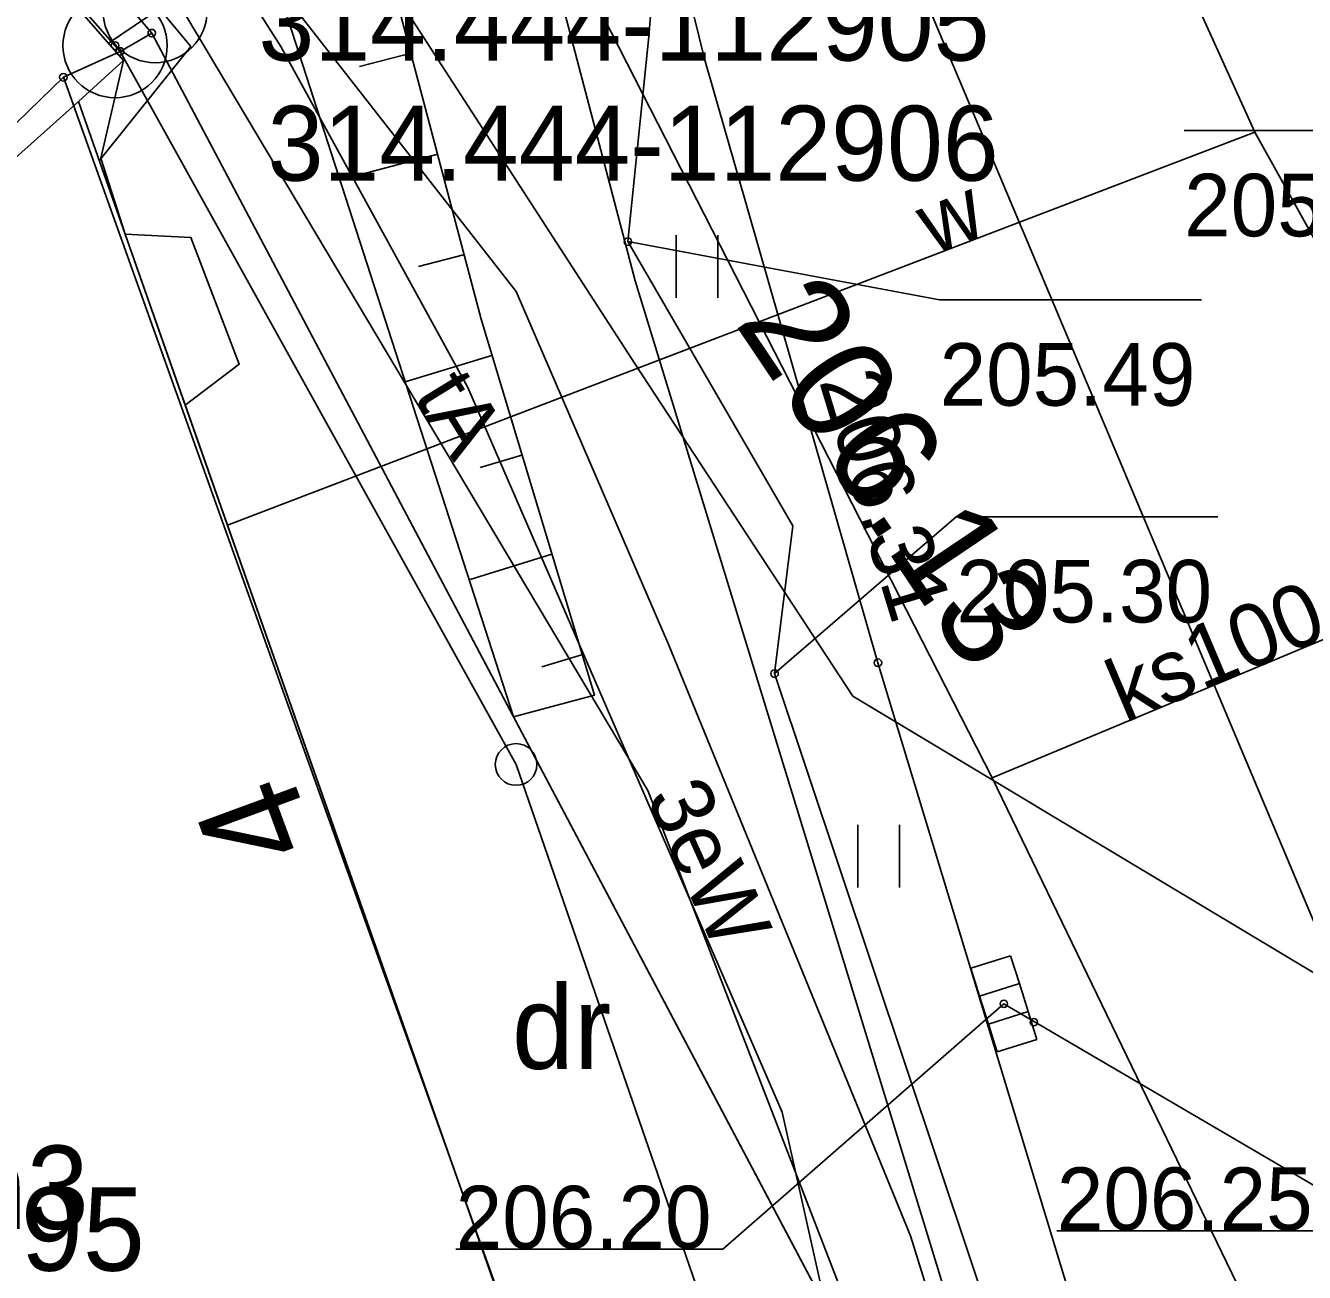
# Model space of a CAD drawing. Extents: x 6512606 to 6513347, y 6022524 to 6022728.
# Drawn here: x 6512836.96 to 6512852.29, y 6022619.43 to 6022634.38 of the extents above; entities that cross this region are included whole.
import ezdxf

# ---------------------------------------------------------------- set-up
doc = ezdxf.new("R2010")
doc.units = 0
for name, color, linetype in [('121-Punkt osnowy szczegółowej', 7, 'Continuous'), ('121-Punkt osnowy szczegółowej-Atr103', 7, 'Continuous'), ('202-punkt graniczny', 7, 'Continuous'), ('203-punkt graniczny', 7, 'Continuous'), ('210-oznaczenie konturu użytku gruntowego', 7, 'Continuous'), ('216-obręb ewidencyjny', 7, 'Continuous'), ('217-kontur klasyfikacyjny', 7, 'Continuous'), ('218-kontur użytku gruntowego', 7, 'Continuous'), ('219-działka ewidencyjna', 7, 'Continuous'), ('238-Punkt adresowy budynku', 7, 'Continuous'), ('312-budynek ewidencyjny', 7, 'Continuous'), ('312-oznaczenie budynku ewidencyjnego', 7, 'Continuous'), ('312-oznaczenie budynku ewidencyjnego-Atr117', 7, 'Continuous'), ('4', 7, 'Continuous'), ('423-Schody przy drogach  chodnikach', 7, 'Continuous'), ('820-Skarpa nieumocniona', 7, 'Continuous'), ('823-Szczyt skarpy nieumocninej', 7, 'Continuous'), ('824-Podnóże skarpy nieumocninej', 7, 'Continuous'), ('940-Trawnik symb. poj.', 7, 'Continuous'), ('chodnik (powierzchnia)', 7, 'Continuous'), ('Default', 7, 'Continuous'), ('kratka ściekowa (punkt)', 7, 'Continuous'), ('krawężnik (linia)', 7, 'Continuous'), ('przewód ciepłowniczy (linia)', 7, 'Continuous'), ('przewód elektroenergetyczny (linia)', 7, 'Continuous'), ('przewód elektroenergetyczny (linia)-Atr1', 7, 'Continuous'), ('przewód gazowy (linia)', 7, 'Continuous'), ('przewód kanalizacyjny (linia)', 7, 'Continuous'), ('przewód kanalizacyjny (linia)-Atr1', 7, 'Continuous'), ('przewód telekomunikacyjny (linia)', 7, 'Continuous'), ('przewód telekomunikacyjny (linia)-Atr1', 7, 'Continuous'), ('przewód wodociągowy (linia)', 7, 'Continuous'), ('przewód wodociągowy (linia)-Atr1', 7, 'Continuous'), ('punkt o określonej wysokości (sieć gazowa)', 7, 'Continuous'), ('punkt o określonej wysokości (sieć gazowa)-Atr2', 7, 'Continuous'), ('punkt o określonej wysokości (sieć gazowa)-Atr3', 7, 'Continuous'), ('punkt o określonej wysokości (sieć kanalizacyjna)', 7, 'Continuous'), ('punkt o określonej wysokości (sieć kanalizacyjna)-Atr2', 7, 'Continuous'), ('punkt o określonej wysokości (sieć wodociągowa)', 7, 'Continuous'), ('punkt wysokościowy sztuczny', 7, 'Continuous'), ('punkt wysokościowy sztuczny-Atr2', 7, 'Continuous'), ('rura ochronna - przewód gazowy (linia)', 7, 'Continuous')]:
    doc.layers.add(name, color=color, linetype=linetype)

# ---------------------------------------------------------------- blocks, each defined once
blk = doc.blocks.new('203')
at = {"layer": 'Default'}
blk.add_circle((0, 0), 0.45, dxfattribs=at)
blk = doc.blocks.new('202')
at = {"layer": 'Default'}
blk.add_circle((0, 0), 2.5, dxfattribs=at)
blk = doc.blocks.new('PW01')
at = {"layer": 'Default'}
blk.add_circle((0, 0), 0.45, dxfattribs=at)
blk = doc.blocks.new('US05')
at = {"layer": 'Default'}
for p, q in [((-5.25, -2.5), (-5.25, 2.5)), ((-5.25, 2.5), (-1.75, 2.5)), ((-1.75, -2.5), (-1.75, 2.5)), ((-1.75, 2.5), (1.75, 2.5)), ((1.75, -2.5), (1.75, 2.5)), ((1.75, 2.5), (5.25, 2.5)), ((5.25, -2.5), (5.25, 2.5)), ((-5.25, -2.5), (-1.75, -2.5)), ((-1.75, -2.5), (1.75, -2.5)), ((1.75, -2.5), (5.25, -2.5))]:
    blk.add_line(p, q, dxfattribs=at)
blk = doc.blocks.new('940P')
at = {"layer": 'Default'}
for p, q in [((-2.5, -3.75), (-2.5, 3.75)), ((2.5, -3.75), (2.5, 3.75))]:
    blk.add_line(p, q, dxfattribs=at)
blk = doc.blocks.new('PW02')
at = {"layer": 'Default'}
blk.add_circle((0, 0), 0.45, dxfattribs=at)
blk = doc.blocks.new('121')
at = {"layer": 'Default'}
for radius in [6.25, 0.45]:
    blk.add_circle((0, 0), radius, dxfattribs=at)

msp = doc.modelspace()

# ---------------------------------------------------------------- linework, layer by layer
at = {"layer": '216-obręb ewidencyjny'}
for points in [[(6512836.687, 6022675.173), (6512833.61, 6022675.02), (6512828.67, 6022670.98), (6512801.96, 6022670.34), (6512810.18, 6022663.28), (6512825.37, 6022649.66), (6512838.47, 6022634.29), (6512852.25, 6022608.25), (6512853.17, 6022604.51), (6512855.78, 6022583.95), (6512858.85, 6022571.74), (6512828.23, 6022562.62), (6512818.47, 6022559.72), (6512824.714, 6022553.406)], [(6512852.25, 6022608.25), (6512838.47, 6022634.29), (6512825.37, 6022649.66), (6512810.18, 6022663.28), (6512801.96, 6022670.34), (6512796.96, 6022674.74), (6512790.49, 6022674.74), (6512785.56, 6022674.74), (6512768.24, 6022674.27), (6512754.87, 6022673.72), (6512745.51, 6022673.33), (6512735.76, 6022672.94), (6512730.35, 6022672.71), (6512725.78, 6022672.95), (6512702.575, 6022674.177)]]:
    msp.add_lwpolyline(points, dxfattribs=at)
at = {"layer": '217-kontur klasyfikacyjny'}
for points in [[(6512837.41, 6022633.76), (6512831.54, 6022628.06)], [(6512848.55, 6022602.62), (6512837.41, 6022633.76)]]:
    msp.add_lwpolyline(points, dxfattribs=at)
at = {"layer": '218-kontur użytku gruntowego'}
for points in [[(6512838.47, 6022634.29), (6512825.37, 6022649.66)], [(6512825.37, 6022649.66), (6512838.47, 6022634.29)], [(6512838.09, 6022634.07), (6512824.77, 6022649.17)], [(6512824.77, 6022649.17), (6512838.09, 6022634.07)], [(6512838.09, 6022634.07), (6512838.47, 6022634.29)], [(6512838.47, 6022634.29), (6512838.09, 6022634.07)], [(6512852.25, 6022608.25), (6512838.47, 6022634.29)], [(6512838.47, 6022634.29), (6512852.25, 6022608.25)], [(6512837.41, 6022633.76), (6512838.09, 6022634.07)], [(6512838.09, 6022634.07), (6512837.41, 6022633.76)], [(6512842.84, 6022625.52), (6512838.09, 6022634.07)], [(6512838.09, 6022634.07), (6512842.84, 6022625.52)], [(6512831.54, 6022628.06), (6512837.41, 6022633.76)], [(6512837.41, 6022633.76), (6512831.54, 6022628.06)], [(6512848.55, 6022602.62), (6512837.41, 6022633.76)], [(6512837.41, 6022633.76), (6512848.55, 6022602.62)], [(6512850.47, 6022603.45), (6512842.84, 6022625.52)], [(6512842.84, 6022625.52), (6512850.47, 6022603.45)]]:
    msp.add_lwpolyline(points, dxfattribs=at)
at = {"layer": '219-działka ewidencyjna'}
for points in [[(6512838.47, 6022634.29), (6512825.37, 6022649.66)], [(6512824.77, 6022649.17), (6512838.09, 6022634.07)], [(6512838.47, 6022634.29), (6512838.09, 6022634.07)], [(6512838.47, 6022634.29), (6512852.25, 6022608.25)], [(6512837.41, 6022633.76), (6512838.09, 6022634.07)], [(6512842.84, 6022625.52), (6512838.09, 6022634.07)], [(6512831.54, 6022628.06), (6512837.41, 6022633.76)], [(6512848.55, 6022602.62), (6512837.41, 6022633.76)], [(6512842.84, 6022625.52), (6512850.47, 6022603.45)]]:
    msp.add_lwpolyline(points, dxfattribs=at)
at = {"layer": '312-budynek ewidencyjny'}
for points in [[(6512824.72, 6022649.31), (6512838.13, 6022633.96)], [(6512838.13, 6022633.96), (6512837.59, 6022633.47)], [(6512837.59, 6022633.47), (6512831.54, 6022628.06)], [(6512831.54, 6022628.06), (6512837.59, 6022633.47)], [(6512837.59, 6022633.47), (6512844.01, 6022615.23)]]:
    msp.add_lwpolyline(points, dxfattribs=at)
at = {"layer": '4'}
for points in [[(6512838.47, 6022634.29), (6512825.37, 6022649.66)], [(6512824.77, 6022649.17), (6512838.09, 6022634.07)], [(6512838.47, 6022634.29), (6512838.09, 6022634.07)], [(6512838.47, 6022634.29), (6512852.25, 6022608.25)], [(6512837.41, 6022633.76), (6512838.09, 6022634.07)], [(6512842.84, 6022625.52), (6512838.09, 6022634.07)], [(6512831.54, 6022628.06), (6512837.41, 6022633.76)], [(6512848.55, 6022602.62), (6512837.41, 6022633.76)], [(6512842.84, 6022625.52), (6512850.47, 6022603.45)]]:
    msp.add_lwpolyline(points, dxfattribs=at)
at = {"layer": '423-Schody przy drogach  chodnikach'}
for p, q in [((6512838.15, 6022631.88), (6512838.87, 6022629.83)), ((6512838.94, 6022631.84), (6512838.15, 6022631.88)), ((6512839.52, 6022630.32), (6512838.94, 6022631.84)), ((6512838.87, 6022629.83), (6512839.52, 6022630.32))]:
    msp.add_line(p, q, dxfattribs=at)
at = {"layer": '820-Skarpa nieumocniona'}
for p, q in [((6512841.58, 6022634.05), (6512840.96, 6022633.89)), ((6512841.9, 6022632.84), (6512840.73, 6022632.53)), ((6512842.21, 6022631.63), (6512841.67, 6022631.49)), ((6512842.56, 6022630.43), (6512841.51, 6022630.11)), ((6512842.91, 6022629.23), (6512842.41, 6022629.08)), ((6512843.27, 6022628.04), (6512842.29, 6022627.74)), ((6512843.64, 6022626.84), (6512843.15, 6022626.69))]:
    msp.add_line(p, q, dxfattribs=at)
at = {"layer": '823-Szczyt skarpy nieumocninej'}
msp.add_lwpolyline([(6512833.8, 6022651.69), (6512834.92, 6022648.19), (6512835.69, 6022646.2), (6512839.8, 6022638.81), (6512840.88, 6022636.68), (6512842.42, 6022630.86), (6512843.78, 6022626.35)], dxfattribs=at)
at = {"layer": '824-Podnóże skarpy nieumocninej'}
msp.add_lwpolyline([(6512843.78, 6022626.35), (6512842.81, 6022626.09), (6512839.81, 6022635.37), (6512839.21, 6022636.76), (6512838.73, 6022638.25), (6512834.42, 6022645.85), (6512833.69, 6022648.06), (6512833.8, 6022651.69)], dxfattribs=at)
at = {"layer": 'chodnik (powierzchnia)'}
msp.add_lwpolyline([(6512845.61, 6022610.5), (6512844.69, 6022613.44), (6512844.06, 6022613.28), (6512843.41, 6022615.01), (6512844.01, 6022615.23), (6512838.87, 6022629.83), (6512839.52, 6022630.32), (6512838.94, 6022631.84), (6512838.15, 6022631.88), (6512837.86, 6022632.79), (6512838.13, 6022633.96), (6512826.89, 6022646.81), (6512825.11, 6022648.85), (6512824.32, 6022649.76), (6512820.29, 6022654.03), (6512817.62, 6022656.88), (6512816.1, 6022658.5), (6512810.3, 6022663.44), (6512802.06, 6022670.47), (6512797.05, 6022674.74)], dxfattribs=at)
for points in [[(6512832.77, 6022654.07), (6512832.63, 6022646.82), (6512837.95, 6022638.9), (6512839.21, 6022636.76), (6512839.81, 6022635.37), (6512842.81, 6022626.09), (6512843.78, 6022626.35), (6512842.42, 6022630.86), (6512840.88, 6022636.68), (6512839.84, 6022641.88), (6512838.78, 6022648.12), (6512838.09, 6022653.46), (6512836.3, 6022653.4), (6512834.86, 6022653.53), (6512833.61, 6022653.83)], [(6512840.07, 6022653.59), (6512840.7, 6022648.33), (6512841.69, 6022642.4), (6512842.69, 6022637.33), (6512844.27, 6022631.32), (6512848.17, 6022618.59), (6512848.25, 6022618.32), (6512848.4, 6022617.84), (6512848.64, 6022617), (6512849.8, 6022613.04), (6512850.26, 6022613.71), (6512850.75, 6022614.71), (6512849.55, 6022618.93), (6512847.18, 6022626.74), (6512845.1, 6022633.98), (6512844.14, 6022637.88), (6512843.35, 6022641.83), (6512842.14, 6022649.32), (6512841.8, 6022651.66)]]:
    msp.add_lwpolyline(points, close=True, dxfattribs=at)
at = {"layer": 'krawężnik (linia)'}
msp.add_lwpolyline([(6512841.8, 6022651.66), (6512842.14, 6022649.32), (6512843.35, 6022641.83), (6512844.14, 6022637.88), (6512845.1, 6022633.98), (6512847.18, 6022626.74), (6512849.55, 6022618.93), (6512850.75, 6022614.71)], dxfattribs=at)
at = {"layer": 'przewód ciepłowniczy (linia)'}
msp.add_lwpolyline([(6512852.19, 6022643.78), (6512837.95, 6022634.17)], dxfattribs=at)
at = {"layer": 'przewód elektroenergetyczny (linia)'}
for points in [[(6512702.569, 6022673.878), (6512710.28, 6022673.25), (6512716.66, 6022675.97), (6512746.13, 6022674.3), (6512752.79, 6022674.32), (6512760.61, 6022675.35), (6512763.38, 6022676.06), (6512798.79, 6022676.04), (6512803.06, 6022673.02), (6512807.84, 6022668.96), (6512815.24, 6022662.53), (6512819.98, 6022657.77), (6512831.6, 6022645.79), (6512834.59, 6022642.25), (6512837.06, 6022638.75), (6512840.02, 6022634.13), (6512842.26, 6022630.04), (6512846.03, 6022621.35), (6512846.58, 6022618.9), (6512847.6, 6022616.23), (6512852.12, 6022605.09)], [(6512802.27, 6022673.66), (6512807.42, 6022670.09), (6512811.38, 6022666.87), (6512814.66, 6022663.43), (6512826.4, 6022651.65), (6512827.82, 6022650.09), (6512834.03, 6022642.46), (6512842.84, 6022631.19), (6512844.67, 6022626.95), (6512847.57, 6022619.87), (6512849.81, 6022612.67), (6512853.56, 6022600.08), (6512856.46, 6022588.83), (6512861.26, 6022569.82), (6512861.768, 6022567.654)]]:
    msp.add_lwpolyline(points, dxfattribs=at)
at = {"layer": 'przewód gazowy (linia)'}
msp.add_lwpolyline([(6512847.18, 6022613.76), (6512846.63, 6022615.41), (6512849.08, 6022617.22), (6512845.94, 6022626.61), (6512846.16, 6022628.38), (6512844.18, 6022631.79), (6512844.23, 6022632.26), (6512844.43, 6022634.25), (6512844.47, 6022634.75), (6512844, 6022635.91), (6512842.48, 6022639.61), (6512842.1, 6022640.54), (6512841.83, 6022641.94), (6512833.52, 6022652.16), (6512828.68, 6022655.12), (6512826.33, 6022655.65), (6512824.93, 6022656.06), (6512819.76, 6022660.64)], dxfattribs=at)
at = {"layer": 'przewód kanalizacyjny (linia)'}
for points in [[(6512853.94, 6022620), (6512836.1, 6022662.34)], [(6512825.42, 6022650.35), (6512838.94, 6022634.13)], [(6512853.7, 6022614.72), (6512848.55, 6022625.36), (6512840.81, 6022640.51)], [(6512837.84, 6022632.76), (6512838.94, 6022634.13)], [(6512848.55, 6022625.36), (6512859.35, 6022629.87)], [(6512848.69, 6022622.65), (6512853.66, 6022619.74)]]:
    msp.add_lwpolyline(points, dxfattribs=at)
at = {"layer": 'przewód telekomunikacyjny (linia)'}
msp.add_lwpolyline([(6512836.6, 6022638.32), (6512844.42, 6022625.21), (6512848.91, 6022613.6), (6512851.86, 6022605.02), (6512853.91, 6022597.19), (6512860.14, 6022571.94), (6512860.33, 6022571.18)], dxfattribs=at)
at = {"layer": 'przewód wodociągowy (linia)'}
for points in [[(6512861.84, 6022602.88), (6512860.4, 6022610.22), (6512855.52, 6022624.92), (6512854.13, 6022628.72), (6512853.02, 6022630.73), (6512851.7, 6022633.1), (6512848.7, 6022639.72)], [(6512855.66, 6022621.07), (6512846.88, 6022626.34), (6512844.27, 6022630.32), (6512839.99, 6022636.93), (6512839.52, 6022638)], [(6512851.7, 6022633.1), (6512839.38, 6022628.39)]]:
    msp.add_lwpolyline(points, dxfattribs=at)
at = {"layer": 'punkt o określonej wysokości (sieć gazowa)-Atr2'}
for points in [[(6512855.49, 6022634.19), (6512854.02, 6022633.12), (6512850.853, 6022633.12)], [(6512844.18, 6022631.79), (6512847.92, 6022631.09), (6512851.061, 6022631.09)], [(6512845.94, 6022626.61), (6512848.12, 6022628.49), (6512851.255, 6022628.49)]]:
    msp.add_lwpolyline(points, dxfattribs=at)
at = {"layer": 'punkt o określonej wysokości (sieć kanalizacyjna)-Atr2'}
for points in [[(6512848.69, 6022622.65), (6512845.32, 6022619.71), (6512842.116, 6022619.71)], [(6512854.42, 6022619.53), (6512852.53, 6022619.93), (6512849.326, 6022619.93)]]:
    msp.add_lwpolyline(points, dxfattribs=at)
at = {"layer": 'rura ochronna - przewód gazowy (linia)'}
msp.add_lwpolyline([(6512844.43, 6022634.25), (6512844.23, 6022632.26)], dxfattribs=at)

# ---------------------------------------------------------------- block references
at = {"layer": '121-Punkt osnowy szczegółowej', "xscale": 0.1, "yscale": 0.10000000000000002}
for p in [(6512838.51, 6022634.56), (6512838.03, 6022634.14)]:
    msp.add_blockref('121', p, dxfattribs=at)
at = {"layer": '202-punkt graniczny', "xscale": 0.1, "yscale": 0.10000000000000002}
msp.add_blockref('202', (6512842.84, 6022625.52), dxfattribs=at)
at = {"layer": '203-punkt graniczny', "xscale": 0.1, "yscale": 0.10000000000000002}
for p in [(6512838.47, 6022634.29), (6512838.09, 6022634.07), (6512837.41, 6022633.76)]:
    msp.add_blockref('203', p, dxfattribs=at)
at = {"layer": '940-Trawnik symb. poj.', "xscale": 0.1, "yscale": 0.10000000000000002}
for p in [(6512845.01, 6022631.49), (6512847.19, 6022624.42)]:
    msp.add_blockref('940P', p, dxfattribs=at)
at = {"layer": 'kratka ściekowa (punkt)', "xscale": 0.1, "yscale": 0.09999999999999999, "rotation": -72.553}
msp.add_blockref('US05', (6512848.69, 6022622.65), dxfattribs=at)
at = {"layer": 'punkt o określonej wysokości (sieć gazowa)', "xscale": 0.1, "yscale": 0.10000000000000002}
for p in [(6512844.18, 6022631.79), (6512845.94, 6022626.61)]:
    msp.add_blockref('PW01', p, dxfattribs=at)
at = {"layer": 'punkt o określonej wysokości (sieć kanalizacyjna)'}
for p, xscale, yscale, rotation in [((6512848.69, 6022622.65), 0.1, 0.09999999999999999, -72.553), ((6512849.05, 6022622.43), 0.10000000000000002, 0.1, -29.547)]:
    msp.add_blockref('PW01', p, dxfattribs=dict(at, xscale=xscale, yscale=yscale, rotation=rotation))
at = {"layer": 'punkt wysokościowy sztuczny', "xscale": 0.1, "yscale": 0.10000000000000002}
msp.add_blockref('PW02', (6512847.18, 6022626.74), dxfattribs=at)

# ---------------------------------------------------------------- texts
at = {"layer": '121-Punkt osnowy szczegółowej-Atr103'}
for s, p in [('314.444-112905', (6512839.75, 6022633.96)), ('314.444-112906', (6512839.86, 6022632.52))]:
    msp.add_text(s, height=0.9, dxfattribs=at).set_placement(p)
at = {"layer": '210-oznaczenie konturu użytku gruntowego'}
msp.add_text('dr', height=1, dxfattribs=at).set_placement((6512842.79, 6022621.87))
at = {"layer": '238-Punkt adresowy budynku'}
msp.add_text('4', height=1.25, rotation=110.214, dxfattribs=at).set_placement((6512840.45, 6022624.58))
at = {"layer": '312-oznaczenie budynku ewidencyjnego'}
msp.add_text('95', height=1, dxfattribs=at).set_placement((6512836.9, 6022619.45))
at = {"layer": '312-oznaczenie budynku ewidencyjnego-Atr117'}
msp.add_text('h3', height=1, dxfattribs=at).set_placement((6512836.227, 6022619.95))
at = {"layer": 'przewód elektroenergetyczny (linia)-Atr1'}
msp.add_text('3eW', height=0.75, rotation=294.239, dxfattribs=at).set_placement((6512844.39, 6022625.13))
at = {"layer": 'przewód kanalizacyjny (linia)-Atr1'}
msp.add_text('ks100', height=0.75, rotation=23.037, dxfattribs=at).set_placement((6512850.14, 6022626.01))
at = {"layer": 'przewód telekomunikacyjny (linia)-Atr1'}
msp.add_text('tA', height=0.75, rotation=301.608, dxfattribs=at).set_placement((6512841.6, 6022629.94))
at = {"layer": 'przewód wodociągowy (linia)-Atr1'}
msp.add_text('w', height=0.75, rotation=21.713, dxfattribs=at).set_placement((6512847.84, 6022631.62))
at = {"layer": 'punkt o określonej wysokości (sieć gazowa)-Atr3'}
for s, p in [('205.40', (6512850.853, 6022631.853)), ('205.49', (6512847.92, 6022629.822)), ('205.30', (6512848.12, 6022627.223))]:
    msp.add_text(s, height=0.75, dxfattribs=at).set_placement(p)
at = {"layer": 'punkt o określonej wysokości (sieć kanalizacyjna)-Atr2'}
for s, p in [('206.25', (6512849.326, 6022619.938)), ('206.20', (6512842.116, 6022619.718))]:
    msp.add_text(s, height=0.75, dxfattribs=at).set_placement(p)
at = {"layer": 'punkt o określonej wysokości (sieć wodociągowa)'}
msp.add_text('206.13', height=1.25, rotation=303.94, dxfattribs=at).set_placement((6512845.45, 6022630.82))
at = {"layer": 'punkt wysokościowy sztuczny-Atr2'}
msp.add_text('206.31', height=0.75, rotation=286.896, dxfattribs=at).set_placement((6512846.47, 6022630.12))

doc.saveas('drawing.dxf')
